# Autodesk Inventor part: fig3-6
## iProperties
Created: 2005-02
Part Number: fig3-6
Document SubType Name: Modeling
Designer: CADCIM
Manufacturer: Standard
Standards Organization: Custom
Author: CADCIM
